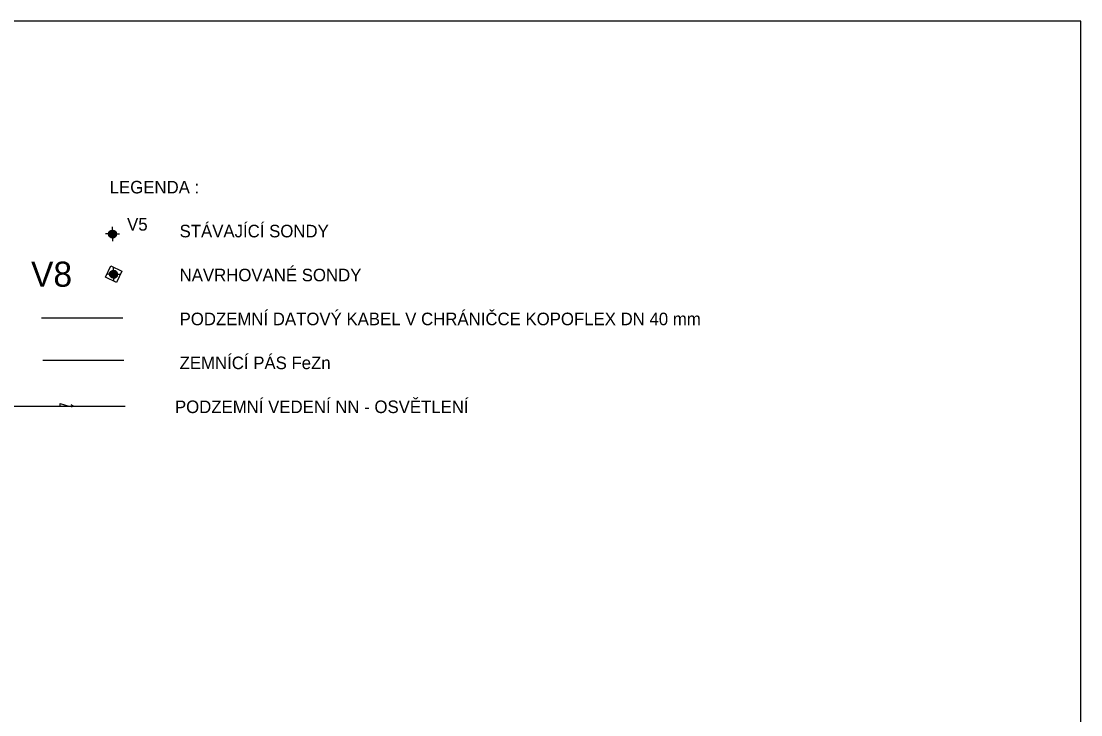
# Model space of a CAD drawing. Extents: x -517788 to -517166, y -1177087 to -1176790.
# Drawn here: x -517662.5 to -517578, y -1176994 to -1176938.7 of the extents above; entities that cross this region are included whole.
import ezdxf

# ---------------------------------------------------------------- set-up
doc = ezdxf.new("R2010")
doc.units = 0
doc.layers.add('mapove znacky', color=7, linetype='Continuous')
doc.layers.add('označení lomového bodu', color=7, linetype='Continuous')

msp = doc.modelspace()

# ---------------------------------------------------------------- linework, layer by layer
at = {"layer": 'mapove znacky'}
for p, q in [((-517655.519, -1176955.63), (-517655.091, -1176955.383)), ((-517655.519, -1176955.711), (-517655.021, -1176955.423)), ((-517655.488, -1176955.531), (-517655.192, -1176955.361)), ((-517655.209, -1176955.36), (-517655.209, -1176955.11)), ((-517655.522, -1176955.672), (-517655.772, -1176955.672)), ((-517655.502, -1176955.782), (-517654.968, -1176955.474)), ((-517655.47, -1176955.844), (-517654.93, -1176955.533)), ((-517655.424, -1176955.899), (-517654.906, -1176955.599)), ((-517655.363, -1176955.944), (-517654.897, -1176955.675)), ((-517655.279, -1176955.977), (-517654.911, -1176955.764)), ((-517655.209, -1176955.985), (-517655.209, -1176956.235)), ((-517655.139, -1176955.977), (-517654.981, -1176955.885)), ((-517654.897, -1176955.672), (-517654.647, -1176955.672)), ((-517655.435, -1176958.836), (-517655.007, -1176958.59)), ((-517655.435, -1176958.917), (-517654.937, -1176958.63)), ((-517655.418, -1176958.988), (-517654.884, -1176958.68)), ((-517655.404, -1176958.738), (-517655.108, -1176958.567)), ((-517655.386, -1176959.051), (-517654.846, -1176958.739)), ((-517655.34, -1176959.105), (-517654.822, -1176958.806)), ((-517655.125, -1176958.566), (-517655.125, -1176958.316)), ((-517655.438, -1176958.879), (-517655.688, -1176958.879)), ((-517655.279, -1176959.151), (-517654.813, -1176958.882)), ((-517655.195, -1176959.183), (-517654.827, -1176958.97)), ((-517655.125, -1176959.191), (-517655.125, -1176959.441)), ((-517655.055, -1176959.183), (-517654.897, -1176959.092)), ((-517654.813, -1176958.879), (-517654.563, -1176958.879))]:
    msp.add_line(p, q, dxfattribs=at)
for centre in [(-517655.209, -1176955.672), (-517655.125, -1176958.879)]:
    msp.add_circle(centre, 0.312, dxfattribs=at)
at = {"layer": 'označení lomového bodu'}
for p, q in [((-517654.399, -1176962.393), (-517660.872, -1176962.393)), ((-517654.296, -1176965.76), (-517660.769, -1176965.76)), ((-517664.996, -1176969.38), (-517654.21, -1176969.38)), ((-517659.375, -1176969.38), (-517659.375, -1176969.191)), ((-517659.375, -1176969.191), (-517658.687, -1176969.38)), ((-517658.325, -1176969.38), (-517658.5, -1176969.296)), ((-517658.325, -1176969.38), (-517658.5, -1176969.464))]:
    msp.add_line(p, q, dxfattribs=at)
for points in [[(-517788.034, -1177087.222), (-517578.034, -1177087.222), (-517578.034, -1176938.722), (-517788.034, -1176938.722)], [(-517654.899, -1176959.536), (-517655.78, -1176959.113), (-517655.352, -1176958.221), (-517654.471, -1176958.644)]]:
    msp.add_lwpolyline(points, close=True, dxfattribs=at)
for points in [[(-517660.769, -1176969.38), (-517660.768, -1176969.38)], [(-517660.243, -1176969.38), (-517659.375, -1176969.38)], [(-517658.687, -1176969.38), (-517658.325, -1176969.38)], [(-517658.059, -1176969.38), (-517657.275, -1176969.38)], [(-517656.792, -1176969.38), (-517655.882, -1176969.38)], [(-517655.357, -1176969.38), (-517654.44, -1176969.38)]]:
    msp.add_lwpolyline(points, dxfattribs=at)

# ---------------------------------------------------------------- texts
for s, height, p in [('LEGENDA :', 1, (-517655.434, -1176952.443)), ('V5', 1, (-517654.047, -1176955.406)), ('               STÁVAJÍCÍ SONDY', 1, (-517655.434, -1176955.943)), ('V8', 2, (-517661.703, -1176959.878)), ('               NAVRHOVANÉ SONDY', 1, (-517655.434, -1176959.443)), ('               PODZEMNÍ DATOVÝ KABEL V CHRÁNIČCE KOPOFLEX DN 40 mm  ', 1, (-517655.434, -1176962.943)), ('               ZEMNÍCÍ PÁS FeZn      ', 1, (-517655.434, -1176966.443)), ('              PODZEMNÍ VEDENÍ NN - OSVĚTLENÍ', 1, (-517655.434, -1176969.943))]:
    msp.add_text(s, height=height, rotation=360, dxfattribs=at).set_placement(p)

doc.saveas('drawing.dxf')
